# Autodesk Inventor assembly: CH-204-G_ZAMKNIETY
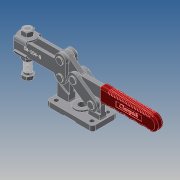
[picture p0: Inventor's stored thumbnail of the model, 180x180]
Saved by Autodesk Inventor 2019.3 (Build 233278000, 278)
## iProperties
Company: ·L?¤¤?
Created: 2010-06
Part Number: CH-204-G_ZAMKNIETY
Material: Ogólny
Description: STEP AP203
Document SubType Name: Assembly
Designer: CADENGINEERING4
Sending System: SolidWorks 2005179
Preprocessor: SwSTEP 2.0
Title: CH-204-G.STEP
Author: ·L?¥Î?
Revision Number: ANY
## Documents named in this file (12)
- E:\STRONA\Horizontal toggle clamp\CH-204-G\CH-204-G_ZAMKNIETY.iam
- E:\STRONA\Horizontal toggle clamp\CH-204-G\204-G-03___.ipt
- E:\STRONA\Horizontal toggle clamp\CH-204-G\M6___.ipt
- E:\STRONA\Horizontal toggle clamp\CH-204-G\CH-FC-12300-01___.ipt
- E:\STRONA\Horizontal toggle clamp\CH-204-G\204-G-02___.ipt
- E:\STRONA\Horizontal toggle clamp\CH-204-G\204-GB-06___.ipt
- E:\STRONA\Horizontal toggle clamp\CH-204-G\204-G-03___.iam
- E:\STRONA\Horizontal toggle clamp\CH-204-G\FW120(2)___.ipt
- E:\STRONA\Horizontal toggle clamp\CH-204-G\CH-FC-12130___.ipt
- E:\STRONA\Horizontal toggle clamp\CH-204-G\201-G-01___.ipt
- E:\STRONA\Horizontal toggle clamp\CH-204-G\204-G-04___.ipt
- E:\STRONA\Horizontal toggle clamp\CH-204-G\204-GB-04___.ipt
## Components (28 placed, 28 different names)
1. 204-G-03_??_1 — Zestawiające:45, Zestawiające:46, Zestawiające:47
2. M6_??_2 — Zestawiające:47, Zestawiające:48
3. CH-FC-12300-01_??_3 — Równoległe:3, Zestawiające:3, Zestawiające:7
4. 204-G-03_??_4 — Zestawiające:51, Zestawiające:52, Zestawiające:53
5. M6_??_5 — Zestawiające:32, Zestawiające:33
6. 204-G-02_??_6 — Zestawiające:34, Równoległe:5, Zestawiające:37, Zestawiające:38, Zestawiające:40
7. 204-GB-06_??_7 — Zestawiające:21, Zestawiające:22
8. 204-GB-06_??_8 — Zestawiające:11, Zestawiające:14, Zestawiające:17, Zestawiające:18
9. 204-GB-06_??_9 — Zestawiające:35, Zestawiające:37
10. 204-G-03_??_10 — Zestawiające:26, Zestawiające:27, Zestawiające:28
11. 204-G-03_??_11 [sub-assembly] — Zestawiające:24, Zestawiające:25, Zestawiające:49, Zestawiające:50, Przejściowe:1
12. FW120(2)_??_13 — Równoległe:1, Równoległe:2, Zestawiające:4, Zestawiające:7, Zestawiające:8
13. FW120(2)_??_14 — Równoległe:2, Zestawiające:1, Zestawiające:5, Zestawiające:6
14. CH-FC-12130_??_15 — Równoległe:3, Zestawiające:1, Zestawiające:2, Zestawiające:3, Zestawiające:4, Zestawiające:9
15. 201-G-01_??_16 — Zestawiające:10, Równoległe:4, Zestawiające:11, Zestawiające:12, Zestawiające:34, Równoległe:5, Zestawiające:35, Zestawiające:36, Przejściowe:1
16. 204-G-02_??_17 — Zestawiające:10, Równoległe:4, Zestawiające:13, Zestawiające:14, Zestawiające:16
17. 204-GB-06_??_18 — Zestawiające:41, Zestawiające:44
18. M6_??_19 — Zestawiające:28, Zestawiające:29
19. 204-GB-06_??_20 — Zestawiające:20, Zestawiające:23, Zestawiające:24
20. 204-GB-06_??_21 — Zestawiające:42, Zestawiające:43, Zestawiające:49
21. 204-G-04_??_22 — Równoległe:1, Zestawiające:5, Zestawiające:8, Zestawiające:9, Zestawiające:39, Zestawiające:40, Zestawiające:41, Zestawiające:42, Zestawiające:43, Zestawiające:44, Zestawiające:45, Zestawiające:46, Zestawiające:48, Zestawiające:50, Zestawiające:51, Zestawiające:52, Zestawiające:54
22. 204-GB-06_??_23 — Zestawiające:12, Zestawiające:13, Zestawiające:15
23. 204-GB-04_??_24 — Zestawiające:15, Zestawiające:16, Zestawiające:19, Zestawiające:20, Zestawiające:23, Zestawiające:25, Zestawiające:26, Zestawiające:27, Zestawiające:30, Zestawiające:31
24. 204-G-03_??_25 — Zestawiające:30, Zestawiające:31, Zestawiające:32
25. 204-GB-04_??_26 — Zestawiające:17, Zestawiające:18, Zestawiające:19, Zestawiające:21, Zestawiające:22, Zestawiające:29, Zestawiające:33
26. 204-GB-06_??_27 — Zestawiające:36, Zestawiające:38, Zestawiające:39
27. CH-FC-12300-01_??_28 — Zestawiające:2, Zestawiające:6
28. M6_??_29 — Zestawiające:53, Zestawiające:54
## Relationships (60: Mate 54, Flush 5, Transitional 1)
- Równoległe:1 [Flush]: FW120(2)_??_13 ↔ 204-G-04_??_22
- Równoległe:2 [Flush]: FW120(2)_??_13 ↔ FW120(2)_??_14
- Równoległe:3 [Flush]: CH-FC-12300-01_??_3 ↔ CH-FC-12130_??_15
- Zestawiające:1 [Mate]: FW120(2)_??_14 ↔ CH-FC-12130_??_15
- Zestawiające:2 [Mate]: CH-FC-12130_??_15 ↔ CH-FC-12300-01_??_28
- Zestawiające:3 [Mate]: CH-FC-12300-01_??_3 ↔ CH-FC-12130_??_15
- Zestawiające:4 [Mate]: FW120(2)_??_13 ↔ CH-FC-12130_??_15
- Zestawiające:5 [Mate]: FW120(2)_??_14 ↔ 204-G-04_??_22
- Zestawiające:6 [Mate]: FW120(2)_??_14 ↔ CH-FC-12300-01_??_28
- Zestawiające:7 [Mate]: CH-FC-12300-01_??_3 ↔ FW120(2)_??_13
- Zestawiające:8 [Mate]: FW120(2)_??_13 ↔ 204-G-04_??_22
- Zestawiające:9 [Mate]: CH-FC-12130_??_15 ↔ 204-G-04_??_22
- Zestawiające:10 [Mate]: 201-G-01_??_16 ↔ 204-G-02_??_17
- Równoległe:4 [Flush]: 201-G-01_??_16 ↔ 204-G-02_??_17
- Zestawiające:11 [Mate]: 204-GB-06_??_8 ↔ 201-G-01_??_16
- Zestawiające:12 [Mate]: 201-G-01_??_16 ↔ 204-GB-06_??_23
- Zestawiające:13 [Mate]: 204-G-02_??_17 ↔ 204-GB-06_??_23
- Zestawiające:14 [Mate]: 204-GB-06_??_8 ↔ 204-G-02_??_17
- Zestawiające:15 [Mate]: 204-GB-06_??_23 ↔ 204-GB-04_??_24
- Zestawiające:16 [Mate]: 204-G-02_??_17 ↔ 204-GB-04_??_24
- Zestawiające:17 [Mate]: 204-GB-06_??_8 ↔ 204-GB-04_??_26
- Zestawiające:18 [Mate]: 204-GB-06_??_8 ↔ 204-GB-04_??_26
- Zestawiające:19 [Mate]: 204-GB-04_??_24 ↔ 204-GB-04_??_26
- Zestawiające:20 [Mate]: 204-GB-06_??_20 ↔ 204-GB-04_??_24
- Zestawiające:21 [Mate]: 204-GB-06_??_7 ↔ 204-GB-04_??_26
- Zestawiające:22 [Mate]: 204-GB-06_??_7 ↔ 204-GB-04_??_26
- Zestawiające:23 [Mate]: 204-GB-06_??_20 ↔ 204-GB-04_??_24
- Zestawiające:24 [Mate]: 204-G-03_??_11 ↔ 204-GB-06_??_20
- Zestawiające:25 [Mate]: 204-G-03_??_11 ↔ 204-GB-04_??_24
- Zestawiające:26 [Mate]: 204-G-03_??_10 ↔ 204-GB-04_??_24
- Zestawiające:27 [Mate]: 204-G-03_??_10 ↔ 204-GB-04_??_24
- Zestawiające:28 [Mate]: 204-G-03_??_10 ↔ M6_??_19
- Zestawiające:29 [Mate]: M6_??_19 ↔ 204-GB-04_??_26
- Zestawiające:30 [Mate]: 204-GB-04_??_24 ↔ 204-G-03_??_25
- Zestawiające:31 [Mate]: 204-GB-04_??_24 ↔ 204-G-03_??_25
- Zestawiające:32 [Mate]: M6_??_5 ↔ 204-G-03_??_25
- Zestawiające:33 [Mate]: M6_??_5 ↔ 204-GB-04_??_26
- Zestawiające:34 [Mate]: 204-G-02_??_6 ↔ 201-G-01_??_16
- Równoległe:5 [Flush]: 204-G-02_??_6 ↔ 201-G-01_??_16
- Zestawiające:35 [Mate]: 204-GB-06_??_9 ↔ 201-G-01_??_16
- Zestawiające:36 [Mate]: 201-G-01_??_16 ↔ 204-GB-06_??_27
- Zestawiające:37 [Mate]: 204-G-02_??_6 ↔ 204-GB-06_??_9
- Zestawiające:38 [Mate]: 204-G-02_??_6 ↔ 204-GB-06_??_27
- Zestawiające:39 [Mate]: 204-G-04_??_22 ↔ 204-GB-06_??_27
- Zestawiające:40 [Mate]: 204-G-02_??_6 ↔ 204-G-04_??_22
- Zestawiające:41 [Mate]: 204-GB-06_??_18 ↔ 204-G-04_??_22
- Zestawiające:42 [Mate]: 204-GB-06_??_21 ↔ 204-G-04_??_22
- Zestawiające:43 [Mate]: 204-GB-06_??_21 ↔ 204-G-04_??_22
- Zestawiające:44 [Mate]: 204-GB-06_??_18 ↔ 204-G-04_??_22
- Zestawiające:45 [Mate]: 204-G-03_??_1 ↔ 204-G-04_??_22
- Zestawiające:46 [Mate]: 204-G-03_??_1 ↔ 204-G-04_??_22
- Zestawiające:47 [Mate]: 204-G-03_??_1 ↔ M6_??_2
- Zestawiające:48 [Mate]: M6_??_2 ↔ 204-G-04_??_22
- Zestawiające:49 [Mate]: 204-G-03_??_11 ↔ 204-GB-06_??_21
- Zestawiające:50 [Mate]: 204-G-03_??_11 ↔ 204-G-04_??_22
- Zestawiające:51 [Mate]: 204-G-03_??_4 ↔ 204-G-04_??_22
- Zestawiające:52 [Mate]: 204-G-03_??_4 ↔ 204-G-04_??_22
- Zestawiające:53 [Mate]: 204-G-03_??_4 ↔ M6_??_29
- Zestawiające:54 [Mate]: 204-G-04_??_22 ↔ M6_??_29
- Przejściowe:1 [Transitional]: 204-G-03_??_11 ↔ 201-G-01_??_16
